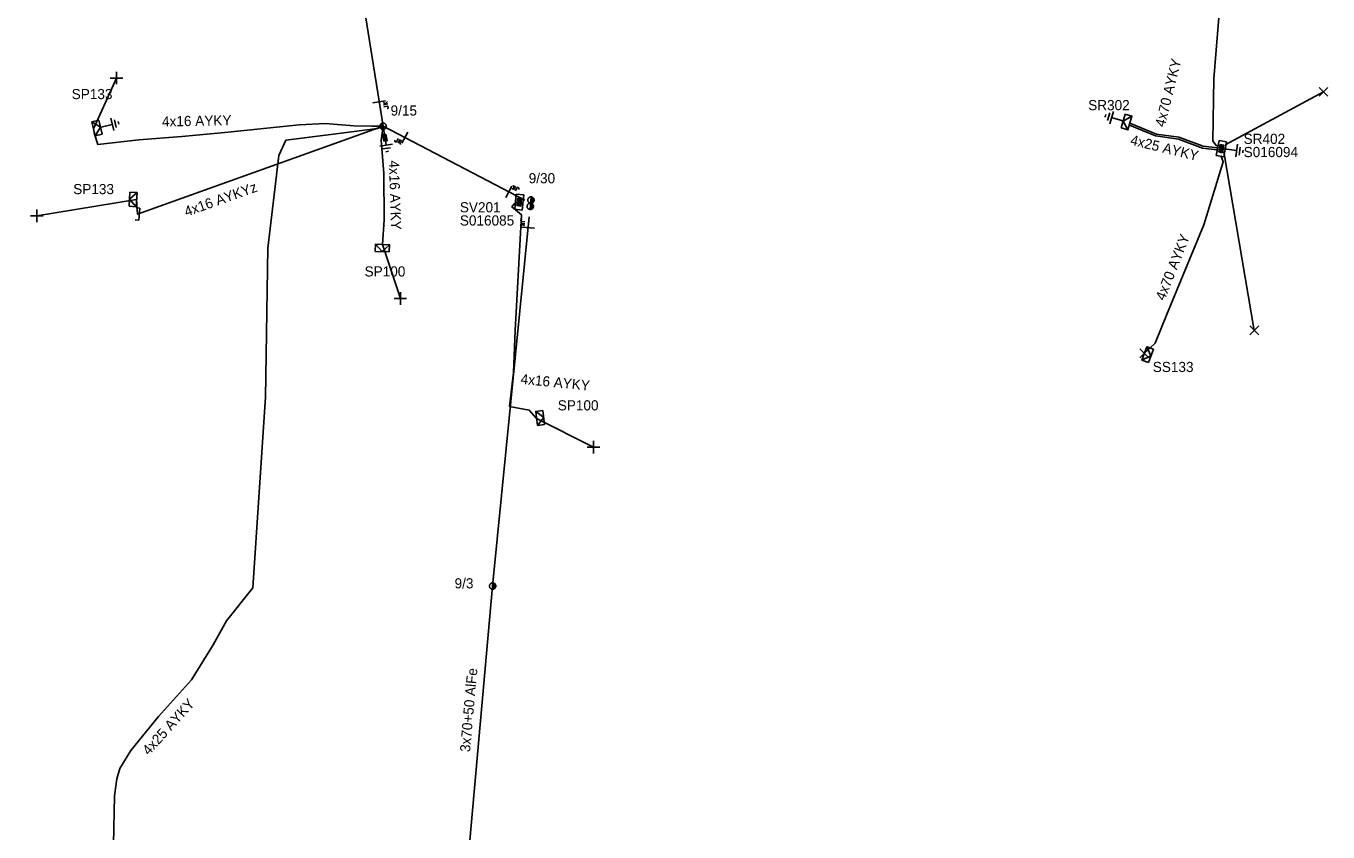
# Model space of a CAD drawing. Extents: x -717562 to -713845, y -1151196 to -1143903.
# Drawn here: x -717009.4 to -716881.2, y -1144904.2 to -1144824.8 of the extents above; entities that cross this region are included whole.
import ezdxf

# ---------------------------------------------------------------- set-up
doc = ezdxf.new("R2010")
doc.units = 0
for name, color, linetype in [('Vrstva 1', 7, 'Continuous'), ('Vrstva 12', 7, 'Continuous'), ('Vrstva 13', 7, 'Continuous'), ('Vrstva 14', 7, 'Continuous'), ('Vrstva 15', 7, 'Continuous'), ('Vrstva 16', 7, 'Continuous'), ('Vrstva 18', 7, 'Continuous'), ('Vrstva 2', 7, 'Continuous'), ('Vrstva 28', 7, 'Continuous'), ('Vrstva 29', 7, 'Continuous'), ('Vrstva 30', 7, 'Continuous'), ('Vrstva 31', 7, 'Continuous'), ('Vrstva 33', 7, 'Continuous'), ('Vrstva 34', 7, 'Continuous'), ('Vrstva 5', 7, 'Continuous'), ('Vrstva 52', 7, 'Continuous'), ('Vrstva 54', 7, 'Continuous'), ('Vrstva 55', 7, 'Continuous'), ('Vrstva 59', 7, 'Continuous'), ('Vrstva 6', 7, 'Continuous'), ('Vrstva 8', 7, 'Continuous'), ('Vrstva 9', 7, 'Continuous')]:
    doc.layers.add(name, color=color, linetype=linetype)

# ---------------------------------------------------------------- blocks, each defined once
blk = doc.blocks.new('NN440')
at = {"layer": 'Vrstva 2'}
for points in [[(0.63, 0), (0.63, 0.06), (0.62, 0.13), (0.6, 0.19), (0.58, 0.25), (0.55, 0.31), (0.51, 0.37), (0.47, 0.42), (0.42, 0.46), (0.37, 0.51), (0.32, 0.54), (0.26, 0.57), (0.2, 0.59), (0.13, 0.61), (0.07, 0.62), (0, 0.63), (-0.06, 0.62), (-0.13, 0.61), (-0.19, 0.59), (-0.26, 0.57), (-0.31, 0.54), (-0.37, 0.51), (-0.42, 0.46), (-0.47, 0.42), (-0.51, 0.37), (-0.54, 0.31), (-0.57, 0.25), (-0.6, 0.19), (-0.62, 0.13), (-0.63, 0.06), (-0.63, 0), (-0.63, -0.07), (-0.62, -0.14), (-0.6, -0.2), (-0.57, -0.26), (-0.54, -0.32), (-0.51, -0.37), (-0.47, -0.43), (-0.42, -0.47), (-0.37, -0.51), (-0.31, -0.55), (-0.26, -0.58), (-0.19, -0.6), (-0.13, -0.62), (-0.06, -0.63), (0, -0.63), (0.07, -0.63), (0.13, -0.62), (0.2, -0.6), (0.26, -0.58), (0.32, -0.55), (0.37, -0.51), (0.42, -0.47), (0.47, -0.43), (0.51, -0.37), (0.55, -0.32), (0.58, -0.26), (0.6, -0.2), (0.62, -0.14), (0.63, -0.07), (0.63, 0)], [(-0.63, 0), (0.63, 0)], [(-0.6, -0.18), (0.57, -0.18)], [(-0.51, -0.32), (0.5, -0.32)], [(-0.37, -0.47), (0.35, -0.47)]]:
    blk.add_lwpolyline(points, dxfattribs=at)
blk = doc.blocks.new('NN450')
at = {"layer": 'Vrstva 2'}
for points in [[(0, 0), (0, 0.07), (-0.01, 0.13), (-0.03, 0.19), (-0.05, 0.25), (-0.08, 0.31), (-0.12, 0.37), (-0.16, 0.42), (-0.21, 0.46), (-0.26, 0.51), (-0.31, 0.54), (-0.37, 0.57), (-0.43, 0.59), (-0.5, 0.61), (-0.56, 0.62), (-0.63, 0.62), (-0.69, 0.62), (-0.75, 0.61), (-0.82, 0.59), (-0.88, 0.57), (-0.94, 0.54), (-0.99, 0.51), (-1.04, 0.46), (-1.09, 0.42), (-1.13, 0.37), (-1.17, 0.31), (-1.2, 0.25), (-1.22, 0.19), (-1.24, 0.13), (-1.25, 0.07), (-1.25, 0), (-1.25, -0.07), (-1.24, -0.13), (-1.22, -0.19), (-1.2, -0.25), (-1.17, -0.31), (-1.13, -0.37), (-1.09, -0.42), (-1.04, -0.46), (-0.99, -0.51), (-0.94, -0.54), (-0.88, -0.57), (-0.82, -0.59), (-0.75, -0.61), (-0.69, -0.62), (-0.62, -0.63), (-0.56, -0.62), (-0.5, -0.61), (-0.43, -0.59), (-0.37, -0.57), (-0.31, -0.54), (-0.26, -0.51), (-0.21, -0.46), (-0.16, -0.42), (-0.12, -0.37), (-0.08, -0.31), (-0.05, -0.25), (-0.03, -0.19), (-0.01, -0.13), (0, -0.07), (0, 0)], [(1.25, 0), (1.25, 0.07), (1.24, 0.13), (1.22, 0.19), (1.2, 0.25), (1.17, 0.31), (1.13, 0.37), (1.09, 0.42), (1.04, 0.46), (0.99, 0.51), (0.94, 0.54), (0.88, 0.57), (0.82, 0.59), (0.75, 0.61), (0.69, 0.62), (0.62, 0.62), (0.56, 0.62), (0.5, 0.61), (0.43, 0.59), (0.37, 0.57), (0.31, 0.54), (0.26, 0.51), (0.21, 0.46), (0.16, 0.42), (0.12, 0.37), (0.08, 0.31), (0.05, 0.25), (0.03, 0.19), (0.01, 0.13), (0, 0.07), (0, 0), (0, -0.07), (0.01, -0.13), (0.03, -0.19), (0.05, -0.25), (0.08, -0.31), (0.12, -0.37), (0.16, -0.42), (0.21, -0.46), (0.26, -0.51), (0.31, -0.54), (0.37, -0.57), (0.43, -0.59), (0.5, -0.61), (0.56, -0.62), (0.63, -0.63), (0.69, -0.62), (0.75, -0.61), (0.82, -0.59), (0.88, -0.57), (0.94, -0.54), (0.99, -0.51), (1.04, -0.46), (1.09, -0.42), (1.13, -0.37), (1.17, -0.31), (1.2, -0.25), (1.22, -0.19), (1.24, -0.13), (1.25, -0.07), (1.25, 0)], [(-1.25, 0), (1.25, 0)], [(-1.23, -0.16), (-0.02, -0.16)], [(-1.16, -0.32), (-0.09, -0.32)], [(-1.03, -0.47), (-0.22, -0.47)], [(0.02, -0.16), (1.23, -0.16)], [(0.09, -0.32), (1.16, -0.32)], [(0.22, -0.47), (1.03, -0.47)]]:
    blk.add_lwpolyline(points, dxfattribs=at)
blk = doc.blocks.new('NN840')
at = {"layer": 'Vrstva 15'}
for points in [[(0, 0.62), (0, -0.63)], [(-0.75, -0.71), (-0.75, -0.66)], [(-0.73, -0.76), (-0.75, -0.71)], [(-0.66, -0.8), (-0.73, -0.76)], [(-0.63, -0.8), (-0.66, -0.8)], [(-0.56, -0.76), (-0.63, -0.8)], [(-0.54, -0.71), (-0.56, -0.76)], [(-0.54, -0.38), (-0.54, -0.71)], [(-0.33, -0.38), (-0.33, -0.8)], [(-0.33, -0.64), (-0.13, -0.38)], [(-0.26, -0.56), (-0.09, -0.8)]]:
    blk.add_lwpolyline(points, dxfattribs=at)
blk = doc.blocks.new('NN800')
at = {"layer": 'Vrstva 1'}
for points in [[(-0.44, 0.44), (0.44, -0.44)], [(-0.44, -0.44), (0.44, 0.44)]]:
    blk.add_lwpolyline(points, dxfattribs=at)
blk = doc.blocks.new('NN820')
at = {"layer": 'Vrstva 13'}
for points in [[(0, 0), (0, -1.05)], [(-0.16, -0.81), (0.16, -0.81)], [(-0.16, -1.47), (-0.16, -0.81)], [(0, -1.05), (-0.06, -0.93)], [(0, -1.05), (0.06, -0.93)], [(0.16, -0.81), (0.16, -1.47)], [(0.16, -1.47), (-0.16, -1.47)], [(0, -1.47), (0, -1.87)]]:
    blk.add_lwpolyline(points, dxfattribs=at)
blk = doc.blocks.new('NN620')
at = {"layer": 'Vrstva 8'}
for points in [[(0.75, 0), (-0.75, 0)], [(-0.75, 0), (-0.75, -0.75)], [(0.75, -0.75), (0.75, 0)], [(-0.75, -0.75), (0.75, -0.75)], [(0.37, -0.18), (-0.38, -0.18)], [(-0.38, -0.18), (-0.38, -0.56)], [(-0.38, -0.56), (0.37, -0.56)], [(0.32, -0.23), (-0.33, -0.23)], [(-0.33, -0.23), (-0.33, -0.51)], [(-0.33, -0.51), (0.32, -0.51)], [(0.27, -0.27), (-0.28, -0.27)], [(-0.28, -0.27), (-0.28, -0.46)], [(-0.28, -0.46), (0.27, -0.46)], [(0.23, -0.32), (-0.23, -0.32)], [(-0.23, -0.32), (-0.23, -0.42)], [(-0.23, -0.42), (0.23, -0.42)], [(-0.19, -0.37), (0.19, -0.37)], [(0.23, -0.42), (0.23, -0.32)], [(0.27, -0.46), (0.27, -0.27)], [(0.32, -0.51), (0.32, -0.23)], [(0.37, -0.56), (0.37, -0.18)]]:
    blk.add_lwpolyline(points, dxfattribs=at)
blk = doc.blocks.new('NN630')
at = {"layer": 'Vrstva 9'}
for points in [[(0, -0.7), (-0.7, 0)], [(-0.7, -0.7), (-0.7, 0), (0.7, 0), (0.7, -0.7)], [(-0.7, -0.7), (0.7, -0.7)], [(0, -0.7), (0.7, 0)]]:
    blk.add_lwpolyline(points, dxfattribs=at)
blk = doc.blocks.new('NN810')
at = {"layer": 'Vrstva 14'}
for points in [[(0, -0.64), (0, -1.89)], [(0.63, -1.89), (-0.62, -1.89)], [(0.39, -2.2), (-0.4, -2.2)], [(0, -2.52), (-0.12, -2.52)], [(0.14, -2.52), (0, -2.52)]]:
    blk.add_lwpolyline(points, dxfattribs=at)
blk = doc.blocks.new('NN515')
at = {"layer": 'Vrstva 2'}
for points in [[(-0.59, 0.18), (0.59, 0.18)], [(-0.59, 0.18), (-0.59, -0.18)], [(0.59, 0.18), (0.59, -0.18)]]:
    blk.add_lwpolyline(points, dxfattribs=at)

msp = doc.modelspace()

# ---------------------------------------------------------------- linework, layer by layer
at = {"layer": 'Vrstva 1'}
for points in [[(-716960.32, -1144841.93), (-716974.29, -1144834.64), (-716978.72, -1144806.92)], [(-716967.53, -1144931.61), (-716966.2, -1144910.14), (-716963.5, -1144879.93), (-716959.89, -1144843.56)]]:
    msp.add_lwpolyline(points, dxfattribs=at)
at = {"layer": 'Vrstva 5'}
for points in [[(-716888.22, -1144761.25), (-716888.58, -1144762.29), (-716888.59, -1144762.7), (-716889.19, -1144766.45), (-716889.61, -1144771.07), (-716889.58, -1144793.7), (-716888.91, -1144802.96), (-716890.08, -1144809.67), (-716891.32, -1144816.71), (-716892.04, -1144824.33), (-716892.47, -1144829.96), (-716892.58, -1144836.07), (-716892.26, -1144836.54), (-716892.03, -1144836.56)], [(-716892.16, -1144836.97), (-716893.61, -1144836.8), (-716895.97, -1144835.9), (-716898.22, -1144835.6), (-716900.8, -1144834.52)], [(-716900.75, -1144834.33), (-716898.14, -1144835.41), (-716895.92, -1144835.71), (-716893.54, -1144836.61), (-716892.11, -1144836.77)]]:
    msp.add_lwpolyline(points, dxfattribs=at)
at = {"layer": 'Vrstva 52'}
for points in [[(-716974.29, -1144834.64), (-716974.85, -1144834.87), (-716979.71, -1144835.48), (-716983.86, -1144836.02), (-716984.57, -1144837.52), (-716985.63, -1144846.66), (-716985.88, -1144861.33), (-716987.12, -1144880.09), (-716989.7, -1144883.35), (-716991.01, -1144885.73), (-716993.14, -1144889.16), (-716996.41, -1144892.78), (-716999.13, -1144896.11), (-717000.21, -1144897.91), (-717000.51, -1144898.92), (-717000.75, -1144900.59), (-717000.84, -1144905.38), (-717002.58, -1144906.97), (-717004.13, -1144908.42), (-717005.67, -1144909.9), (-717006.59, -1144910.44), (-717007.51, -1144910.72), (-717009.45, -1144910.32)], [(-716974.29, -1144834.64), (-716975.4, -1144834.64), (-716977.17, -1144834.6), (-716979.96, -1144834.36), (-716982.55, -1144834.5), (-716989.87, -1144835.27), (-716994.1, -1144835.66), (-716998.34, -1144835.99), (-717002.37, -1144836.45), (-717002.72, -1144835.43), (-717002.8, -1144834.9)], [(-716974.29, -1144834.64), (-716974.47, -1144836.02), (-716974.22, -1144839.28), (-716974.18, -1144843.86), (-716974.35, -1144846.29)], [(-716891.81, -1144837.52), (-716891.57, -1144838.14), (-716893.46, -1144844.36), (-716897.16, -1144853.25), (-716898.25, -1144856.02), (-716899.33, -1144857.01)], [(-716961.3, -1144842.21), (-716961.6, -1144842.59), (-716960.66, -1144843.36), (-716961.28, -1144854.77), (-716961.45, -1144858.91), (-716961.83, -1144862.24), (-716959.9, -1144862.59), (-716959.17, -1144863.42)]]:
    msp.add_lwpolyline(points, dxfattribs=at)
at = {"layer": 'Vrstva 54'}
msp.add_lwpolyline([(-716974.29, -1144834.64), (-716998.47, -1144843.29), (-716998.56, -1144841.87)], dxfattribs=at)
at = {"layer": 'Vrstva 59'}
for points in [[(-717002.8, -1144834.9), (-717000.55, -1144829.89)], [(-716891.37, -1144836.47), (-716881.69, -1144831.25)], [(-716891.51, -1144837.16), (-716888.5, -1144854.75)], [(-716998.56, -1144841.87), (-717008.39, -1144843.45)], [(-716974.35, -1144846.29), (-716972.59, -1144851.61)], [(-716959.17, -1144863.42), (-716953.56, -1144866.25)]]:
    msp.add_lwpolyline(points, dxfattribs=at)

# ---------------------------------------------------------------- block references
at = {"layer": 'Vrstva 13'}
for name, p, xscale, yscale, rotation in [('NN440', (-716974.29, -1144834.64), 0.5, 0.5, -80.92020277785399), ('NN450', (-716959.76, -1144842.22), 0.5, 0.5000000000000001, 84.33604445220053), ('NN440', (-716963.5, -1144879.93), 0.5000000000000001, 0.5, 84.89279440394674)]:
    msp.add_blockref(name, p, dxfattribs=dict(at, xscale=xscale, yscale=yscale, rotation=rotation))
at = {"layer": 'Vrstva 13', "rotation": -93.86374440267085}
msp.add_blockref('NN515', (-716998.47, -1144843.29), dxfattribs=at)
at = {"layer": 'Vrstva 15'}
for p, rotation in [((-717002.8, -1144834.9), 103.49928725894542), ((-716900.75, -1144834.33), -106.73806301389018), ((-716974.29, -1144834.64), 9.079797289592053), ((-716892.11, -1144836.77), 81.81368050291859)]:
    msp.add_blockref('NN810', p, dxfattribs=dict(at, rotation=rotation))
at = {"layer": 'Vrstva 16', "rotation": 9.079797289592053}
msp.add_blockref('NN820', (-716974.29, -1144834.64), dxfattribs=at)
at = {"layer": 'Vrstva 18'}
for p, rotation in [((-716974.67, -1144832.25), 99.07979724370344), ((-716972.14, -1144835.76), -27.550116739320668), ((-716961.91, -1144841.1), 152.44988326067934), ((-716960, -1144844.63), -95.66395561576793)]:
    msp.add_blockref('NN840', p, dxfattribs=dict(at, rotation=rotation))
at = {"layer": 'Vrstva 28'}
for p, rotation in [((-716892.11, -1144836.77), 79.74360425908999), ((-716960.51, -1144842.15), -95.66400003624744)]:
    msp.add_blockref('NN620', p, dxfattribs=dict(at, rotation=rotation))
at = {"layer": 'Vrstva 31'}
for p, rotation in [((-716900.75, -1144834.33), -105.8809839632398), ((-717002.8, -1144834.9), 103.96480951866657), ((-716998.56, -1144841.87), -93.86374440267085), ((-716974.35, -1144846.29), -1.9135165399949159), ((-716899.33, -1144857.01), 69.55262289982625), ((-716959.17, -1144863.42), 97.58349446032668)]:
    msp.add_blockref('NN630', p, dxfattribs=dict(at, rotation=rotation))
at = {"layer": 'Vrstva 34', "rotation": 45}
for p in [(-717000.55, -1144829.89), (-717008.39, -1144843.45), (-716972.59, -1144851.61), (-716953.56, -1144866.25)]:
    msp.add_blockref('NN800', p, dxfattribs=at)
at = {"layer": 'Vrstva 34'}
for p in [(-716881.69, -1144831.25), (-716888.5, -1144854.75), (-716899.33, -1144857.01)]:
    msp.add_blockref('NN800', p, dxfattribs=at)

# ---------------------------------------------------------------- texts
at = {"layer": 'Vrstva 12'}
for s, p in [('9/15', (-716973.55, -1144833.59)), ('9/30', (-716959.95, -1144840.26)), ('9/3', (-716967.25, -1144880.16))]:
    msp.add_text(s, height=1, dxfattribs=at).set_placement(p)
at = {"layer": 'Vrstva 2'}
msp.add_text('3x70+50 AlFe', height=1, rotation=84.893, dxfattribs=at).set_placement((-716965.73, -1144896.31))
at = {"layer": 'Vrstva 29'}
for s, p in [('S016094', (-716889.55, -1144837.68)), ('S016085', (-716966.73, -1144844.42))]:
    msp.add_text(s, height=1, dxfattribs=at).set_placement(p)
at = {"layer": 'Vrstva 30'}
for s, p in [('SR402', (-716889.55, -1144836.38)), ('SV201', (-716966.73, -1144843.12))]:
    msp.add_text(s, height=1, dxfattribs=at).set_placement(p)
at = {"layer": 'Vrstva 33'}
for s, p in [('SP133', (-717004.95, -1144831.97)), ('SR302', (-716904.86, -1144833.06)), ('SP133', (-717004.8, -1144841.33)), ('SP100', (-716976.11, -1144849.44)), ('SS133', (-716898.5, -1144858.85)), ('SP100', (-716957.09, -1144862.63))]:
    msp.add_text(s, height=1, dxfattribs=at).set_placement(p)
at = {"layer": 'Vrstva 54'}
for s, rotation, p in [('4x16 AYKY', 1.027, (-716996.05, -1144834.67)), ('4x16 AYKY', 271.886, (-716973.72, -1144838.02)), ('4x70 AYKY', 68.51, (-716897.34, -1144851.88)), ('4x16 AYKY', 354.294, (-716960.78, -1144860.01)), ('4x25 AYKY', 47.904, (-716997.36, -1144896.66))]:
    msp.add_text(s, height=1, rotation=rotation, dxfattribs=at).set_placement(p)
at = {"layer": 'Vrstva 55'}
msp.add_text('4x16 AYKYz', height=1, rotation=19.67, dxfattribs=at).set_placement((-716993.65, -1144843.56))
at = {"layer": 'Vrstva 6'}
for s, rotation, p in [('4x70 AYKY', 76.02, (-716897.33, -1144834.78)), ('4x25 AYKY', 346.273, (-716900.78, -1144836.44))]:
    msp.add_text(s, height=1, rotation=rotation, dxfattribs=at).set_placement(p)

doc.saveas('drawing.dxf')
